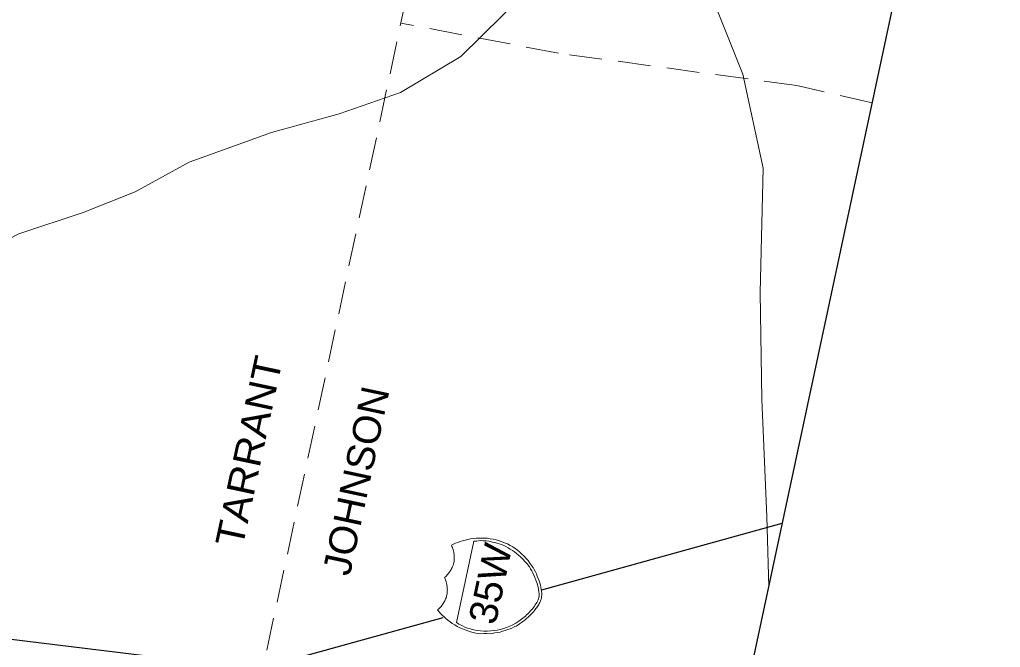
# Model space of a CAD drawing. Extents: x 2363411 to 2369126, y 6976878 to 6988319.
# Drawn here: x 2368374.1 to 2368553.7, y 6987987.6 to 6988102.7 of the extents above; entities that cross this region are included whole.
import ezdxf

# ---------------------------------------------------------------- set-up
doc = ezdxf.new("R2010")
doc.units = 0
doc.header["$LTSCALE"] = 2
doc.linetypes.add('MEDIUM_DASHED', pattern=[4.5, 3, -1.5])
doc.layers.add('62', color=7, linetype='Continuous', lineweight=13)
doc.layers.add('63', color=7, linetype='Continuous', lineweight=13)

msp = doc.modelspace()

# ---------------------------------------------------------------- linework, layer by layer
at = {"layer": '62', "linetype": 'MEDIUM_DASHED'}
msp.add_line((2368374.263, 6987775.914), (2368468.206, 6988215.584), dxfattribs=at)
at = {"layer": '62', "lineweight": 25}
msp.add_line((2368469.733, 6987998.18), (2368513.787, 6988010.419), dxfattribs=at)
for points in [[(2368004.774, 6987854.862), (2368459.776, 6987757.642), (2368553.719, 6988197.31), (2368098.715, 6988294.53)], [(2368243.911, 6988012.604), (2368291.866, 6988003.347), (2368346.556, 6987992.355), (2368417.518, 6987983.635), (2368451.697, 6987993.151)]]:
    msp.add_lwpolyline(points, dxfattribs=at)
at = {"layer": '62'}
for points in [[(2368423.495, 6988182.612), (2368431.049, 6988175.317), (2368445.358, 6988162.592), (2368462.419, 6988152.736), (2368475.776, 6988146.66), (2368485.116, 6988127.592), (2368494.927, 6988125.354), (2368500.711, 6988107.416), (2368506.585, 6988092.7), (2368510.293, 6988075.479), (2368509.748, 6988052.675), (2368510.031, 6988033.104), (2368510.965, 6988011.643), (2368511.296, 6987998.756)], [(2368492.126, 6988150.482), (2368487.488, 6988143.215), (2368483.673, 6988134.181), (2368476.579, 6988118.002), (2368468.319, 6988109.277), (2368462.564, 6988103.439), (2368454.914, 6988095.96), (2368443.897, 6988089.32), (2368432.645, 6988085.443), (2368420.226, 6988082.021), (2368405.209, 6988076.579), (2368395.275, 6988071.108), (2368385.769, 6988067.316), (2368374.006, 6988063.41), (2368368.396, 6988060.537), (2368354.465, 6988056.288)], [(2368452.564, 6988001.087), (2368452.692, 6988001.246), (2368452.823, 6988001.425), (2368452.92, 6988001.565), (2368453.05, 6988001.744), (2368453.137, 6988001.932), (2368453.24, 6988002.094), (2368453.321, 6988002.261), (2368453.386, 6988002.454), (2368453.467, 6988002.62), (2368453.554, 6988002.81), (2368453.592, 6988002.986), (2368453.634, 6988003.186), (2368453.673, 6988003.36), (2368453.709, 6988003.534), (2368453.711, 6988003.765), (2368453.702, 6988003.928), (2368453.716, 6988004.109), (2368453.716, 6988004.316), (2368453.691, 6988004.53), (2368453.685, 6988004.715), (2368453.64, 6988004.931), (2368453.612, 6988005.121), (2368453.562, 6988005.316), (2368453.512, 6988005.511), (2368453.461, 6988005.706), (2368453.392, 6988005.927), (2368453.301, 6988006.153), (2368453.208, 6988006.359), (2368453.571, 6988006.556), (2368453.954, 6988006.729), (2368454.357, 6988006.895), (2368454.805, 6988007.051), (2368455.227, 6988007.194), (2368455.691, 6988007.323), (2368456.175, 6988007.429), (2368456.68, 6988007.527), (2368457.2, 6988007.6), (2368457.718, 6988007.651), (2368458.252, 6988007.672), (2368458.759, 6988007.68), (2368459.284, 6988007.66), (2368459.809, 6988007.64), (2368460.321, 6988007.555), (2368460.837, 6988007.492), (2368461.377, 6988007.33), (2368461.924, 6988007.188), (2368462.455, 6988006.985), (2368462.947, 6988006.808), (2368463.457, 6988006.609), (2368463.947, 6988006.32), (2368464.422, 6988006.057), (2368464.866, 6988005.778), (2368465.305, 6988005.453), (2368465.736, 6988005.11), (2368466.121, 6988004.751), (2368466.526, 6988004.387), (2368466.896, 6988003.964), (2368467.241, 6988003.543), (2368467.587, 6988003.103), (2368467.896, 6988002.621), (2368468.143, 6988002.27), (2368468.363, 6988001.902), (2368468.574, 6988001.487), (2368468.768, 6988001.1), (2368468.929, 6988000.675), (2368469.092, 6988000.247), (2368469.237, 6987999.848), (2368469.382, 6987999.451), (2368469.504, 6987999.057), (2368469.585, 6987998.671), (2368469.663, 6987998.287), (2368469.721, 6987997.908), (2368469.742, 6987997.578), (2368469.741, 6987997.257), (2368469.719, 6987996.939), (2368469.686, 6987996.67)], [(2368469.686, 6987996.67), (2368469.625, 6987996.499), (2368469.593, 6987996.346), (2368469.534, 6987996.175), (2368469.457, 6987996.032), (2368469.374, 6987995.863), (2368469.294, 6987995.696), (2368469.179, 6987995.49), (2368469.072, 6987995.304), (2368468.947, 6987995.149), (2368468.837, 6987994.966), (2368468.681, 6987994.766), (2368468.551, 6987994.587), (2368468.414, 6987994.387), (2368468.269, 6987994.236), (2368468.088, 6987994.042), (2368467.931, 6987993.847), (2368467.757, 6987993.677), (2368467.577, 6987993.484), (2368467.383, 6987993.321), (2368467.209, 6987993.15), (2368467.032, 6987992.979), (2368466.815, 6987992.821), (2368466.64, 6987992.65), (2368466.448, 6987992.507), (2368466.23, 6987992.347), (2368466.038, 6987992.204), (2368465.848, 6987992.06), (2368465.638, 6987991.944), (2368465.42, 6987991.784), (2368465.235, 6987991.662), (2368465.028, 6987991.567), (2368464.819, 6987991.452), (2368464.411, 6987991.263), (2368463.93, 6987991.065), (2368463.485, 6987990.909), (2368463.036, 6987990.753), (2368462.568, 6987990.599), (2368462.103, 6987990.468), (2368461.643, 6987990.359), (2368461.168, 6987990.299), (2368460.69, 6987990.217), (2368460.196, 6987990.161), (2368459.692, 6987990.177), (2368459.207, 6987990.166), (2368458.699, 6987990.158), (2368458.226, 6987990.214), (2368457.689, 6987990.284), (2368457.178, 6987990.366), (2368456.68, 6987990.522), (2368456.183, 6987990.673), (2368455.692, 6987990.848), (2368455.204, 6987991.042), (2368454.743, 6987991.257), (2368454.266, 6987991.498), (2368453.816, 6987991.754), (2368453.364, 6987992.012), (2368452.948, 6987992.332), (2368452.55, 6987992.621), (2368452.181, 6987992.931), (2368451.852, 6987993.231), (2368451.511, 6987993.582), (2368451.205, 6987993.854), (2368450.931, 6987994.188), (2368450.678, 6987994.518), (2368450.847, 6987994.666), (2368451.022, 6987994.835), (2368451.176, 6987995.011), (2368451.302, 6987995.168), (2368451.432, 6987995.347), (2368451.556, 6987995.505), (2368451.665, 6987995.688), (2368451.79, 6987995.847), (2368451.871, 6987996.012), (2368451.975, 6987996.174), (2368452.061, 6987996.362), (2368452.122, 6987996.533), (2368452.212, 6987996.747), (2368452.29, 6987996.89), (2368452.328, 6987997.066), (2368452.374, 6987997.285), (2368452.411, 6987997.461), (2368452.449, 6987997.637), (2368452.448, 6987997.844), (2368452.442, 6987998.029), (2368452.456, 6987998.21), (2368452.449, 6987998.396), (2368452.43, 6987998.631), (2368452.426, 6987998.818), (2368452.375, 6987999.013), (2368452.346, 6987999.203), (2368452.3, 6987999.42), (2368452.254, 6987999.636), (2368452.204, 6987999.831), (2368452.133, 6988000.03), (2368452.039, 6988000.236), (2368451.949, 6988000.46), (2368452.116, 6988000.608), (2368452.287, 6988000.756), (2368452.439, 6988000.932), (2368452.564, 6988001.087)]]:
    msp.add_lwpolyline(points, dxfattribs=at)
at = {"layer": '62', "linetype": 'MEDIUM_DASHED'}
msp.add_lwpolyline([(2368530.249, 6988087.461), (2368516.424, 6988090.6), (2368472.799, 6988096.536), (2368443.949, 6988102.056)], dxfattribs=at)
at = {"layer": '62'}
msp.add_lwpolyline([(2368457.299, 6988007.096), (2368454.117, 6987992.197), (2368454.318, 6987992.064), (2368454.584, 6987991.913), (2368454.872, 6987991.759), (2368455.252, 6987991.586), (2368455.669, 6987991.382), (2368456.155, 6987991.186), (2368456.673, 6987991.029), (2368457.292, 6987990.894), (2368457.885, 6987990.772), (2368458.535, 6987990.678), (2368459.146, 6987990.639), (2368459.769, 6987990.643), (2368460.397, 6987990.671), (2368460.984, 6987990.729), (2368461.598, 6987990.805), (2368462.183, 6987990.956), (2368462.745, 6987991.112), (2368463.313, 6987991.291), (2368463.894, 6987991.535), (2368464.452, 6987991.782), (2368464.981, 6987992.106), (2368465.518, 6987992.452), (2368466.008, 6987992.807), (2368466.506, 6987993.208), (2368466.752, 6987993.385), (2368466.963, 6987993.616), (2368467.212, 6987993.816), (2368467.428, 6987994.068), (2368467.635, 6987994.28), (2368467.865, 6987994.505), (2368468.031, 6987994.745), (2368468.242, 6987994.977), (2368468.409, 6987995.217), (2368468.547, 6987995.441), (2368468.716, 6987995.683), (2368468.85, 6987995.883), (2368468.973, 6987996.131), (2368469.063, 6987996.343), (2368469.132, 6987996.559), (2368469.201, 6987996.776), (2368469.245, 6987997.089), (2368469.26, 6987997.475), (2368469.203, 6987997.855), (2368469.154, 6987998.281), (2368469.081, 6987998.685), (2368468.966, 6987999.125), (2368468.827, 6987999.547), (2368468.671, 6987999.993), (2368468.49, 6988000.447), (2368468.284, 6988000.882), (2368468.097, 6988001.29), (2368467.903, 6988001.677), (2368467.71, 6988002.064), (2368467.484, 6988002.411), (2368467.253, 6988002.736), (2368467.049, 6988002.964), (2368466.662, 6988003.415), (2368466.283, 6988003.794), (2368465.906, 6988004.174), (2368465.501, 6988004.536), (2368465.132, 6988004.869), (2368464.735, 6988005.164), (2368464.355, 6988005.427), (2368463.948, 6988005.676), (2368463.562, 6988005.918), (2368463.174, 6988006.14), (2368462.773, 6988006.32), (2368462.349, 6988006.478), (2368461.943, 6988006.632), (2368461.535, 6988006.766), (2368461.119, 6988006.877), (2368460.725, 6988006.962), (2368460.106, 6988007.094), (2368459.571, 6988007.163), (2368459.043, 6988007.184), (2368458.591, 6988007.211), (2368458.17, 6988007.186), (2368457.838, 6988007.141), (2368457.533, 6988007.114)], close=True, dxfattribs=at)
at = {"layer": '63', "linetype": 'MEDIUM_DASHED'}
msp.add_line((2368374.263, 6987775.914), (2368468.206, 6988215.584), dxfattribs=at)
at = {"layer": '63', "lineweight": 25}
msp.add_line((2368469.733, 6987998.18), (2368513.787, 6988010.419), dxfattribs=at)
for points in [[(2368004.774, 6987854.862), (2368459.776, 6987757.642), (2368553.719, 6988197.31), (2368098.715, 6988294.53)], [(2368243.911, 6988012.604), (2368291.866, 6988003.347), (2368346.556, 6987992.355), (2368417.518, 6987983.635), (2368451.697, 6987993.151)]]:
    msp.add_lwpolyline(points, dxfattribs=at)
at = {"layer": '63'}
for points in [[(2368423.495, 6988182.612), (2368431.049, 6988175.317), (2368445.358, 6988162.592), (2368462.419, 6988152.736), (2368475.776, 6988146.66), (2368485.116, 6988127.592), (2368494.927, 6988125.354), (2368500.711, 6988107.416), (2368506.585, 6988092.7), (2368510.293, 6988075.479), (2368509.748, 6988052.675), (2368510.031, 6988033.104), (2368510.965, 6988011.643), (2368511.296, 6987998.756)], [(2368492.126, 6988150.482), (2368487.488, 6988143.215), (2368483.673, 6988134.181), (2368476.579, 6988118.002), (2368468.319, 6988109.277), (2368462.564, 6988103.439), (2368454.914, 6988095.96), (2368443.897, 6988089.32), (2368432.645, 6988085.443), (2368420.226, 6988082.021), (2368405.209, 6988076.579), (2368395.275, 6988071.108), (2368385.769, 6988067.316), (2368374.006, 6988063.41), (2368368.396, 6988060.537), (2368354.465, 6988056.288)], [(2368452.564, 6988001.087), (2368452.692, 6988001.246), (2368452.823, 6988001.425), (2368452.92, 6988001.565), (2368453.05, 6988001.744), (2368453.137, 6988001.932), (2368453.24, 6988002.094), (2368453.321, 6988002.261), (2368453.386, 6988002.454), (2368453.467, 6988002.62), (2368453.554, 6988002.81), (2368453.592, 6988002.986), (2368453.634, 6988003.186), (2368453.673, 6988003.36), (2368453.709, 6988003.534), (2368453.711, 6988003.765), (2368453.702, 6988003.928), (2368453.716, 6988004.109), (2368453.716, 6988004.316), (2368453.691, 6988004.53), (2368453.685, 6988004.715), (2368453.64, 6988004.931), (2368453.612, 6988005.121), (2368453.562, 6988005.316), (2368453.512, 6988005.511), (2368453.461, 6988005.706), (2368453.392, 6988005.927), (2368453.301, 6988006.153), (2368453.208, 6988006.359), (2368453.571, 6988006.556), (2368453.954, 6988006.729), (2368454.357, 6988006.895), (2368454.805, 6988007.051), (2368455.227, 6988007.194), (2368455.691, 6988007.323), (2368456.175, 6988007.429), (2368456.68, 6988007.527), (2368457.2, 6988007.6), (2368457.718, 6988007.651), (2368458.252, 6988007.672), (2368458.759, 6988007.68), (2368459.284, 6988007.66), (2368459.809, 6988007.64), (2368460.321, 6988007.555), (2368460.837, 6988007.492), (2368461.377, 6988007.33), (2368461.924, 6988007.188), (2368462.455, 6988006.985), (2368462.947, 6988006.808), (2368463.457, 6988006.609), (2368463.947, 6988006.32), (2368464.422, 6988006.057), (2368464.866, 6988005.778), (2368465.305, 6988005.453), (2368465.736, 6988005.11), (2368466.121, 6988004.751), (2368466.526, 6988004.387), (2368466.896, 6988003.964), (2368467.241, 6988003.543), (2368467.587, 6988003.103), (2368467.896, 6988002.621), (2368468.143, 6988002.27), (2368468.363, 6988001.902), (2368468.574, 6988001.487), (2368468.768, 6988001.1), (2368468.929, 6988000.675), (2368469.092, 6988000.247), (2368469.237, 6987999.848), (2368469.382, 6987999.451), (2368469.504, 6987999.057), (2368469.585, 6987998.671), (2368469.663, 6987998.287), (2368469.721, 6987997.908), (2368469.742, 6987997.578), (2368469.741, 6987997.257), (2368469.719, 6987996.939), (2368469.686, 6987996.67)], [(2368469.686, 6987996.67), (2368469.625, 6987996.499), (2368469.593, 6987996.346), (2368469.534, 6987996.175), (2368469.457, 6987996.032), (2368469.374, 6987995.863), (2368469.294, 6987995.696), (2368469.179, 6987995.49), (2368469.072, 6987995.304), (2368468.947, 6987995.149), (2368468.837, 6987994.966), (2368468.681, 6987994.766), (2368468.551, 6987994.587), (2368468.414, 6987994.387), (2368468.269, 6987994.236), (2368468.088, 6987994.042), (2368467.931, 6987993.847), (2368467.757, 6987993.677), (2368467.577, 6987993.484), (2368467.383, 6987993.321), (2368467.209, 6987993.15), (2368467.032, 6987992.979), (2368466.815, 6987992.821), (2368466.64, 6987992.65), (2368466.448, 6987992.507), (2368466.23, 6987992.347), (2368466.038, 6987992.204), (2368465.848, 6987992.06), (2368465.638, 6987991.944), (2368465.42, 6987991.784), (2368465.235, 6987991.662), (2368465.028, 6987991.567), (2368464.819, 6987991.452), (2368464.411, 6987991.263), (2368463.93, 6987991.065), (2368463.485, 6987990.909), (2368463.036, 6987990.753), (2368462.568, 6987990.599), (2368462.103, 6987990.468), (2368461.643, 6987990.359), (2368461.168, 6987990.299), (2368460.69, 6987990.217), (2368460.196, 6987990.161), (2368459.692, 6987990.177), (2368459.207, 6987990.166), (2368458.699, 6987990.158), (2368458.226, 6987990.214), (2368457.689, 6987990.284), (2368457.178, 6987990.366), (2368456.68, 6987990.522), (2368456.183, 6987990.673), (2368455.692, 6987990.848), (2368455.204, 6987991.042), (2368454.743, 6987991.257), (2368454.266, 6987991.498), (2368453.816, 6987991.754), (2368453.364, 6987992.012), (2368452.948, 6987992.332), (2368452.55, 6987992.621), (2368452.181, 6987992.931), (2368451.852, 6987993.231), (2368451.511, 6987993.582), (2368451.205, 6987993.854), (2368450.931, 6987994.188), (2368450.678, 6987994.518), (2368450.847, 6987994.666), (2368451.022, 6987994.835), (2368451.176, 6987995.011), (2368451.302, 6987995.168), (2368451.432, 6987995.347), (2368451.556, 6987995.505), (2368451.665, 6987995.688), (2368451.79, 6987995.847), (2368451.871, 6987996.012), (2368451.975, 6987996.174), (2368452.061, 6987996.362), (2368452.122, 6987996.533), (2368452.212, 6987996.747), (2368452.29, 6987996.89), (2368452.328, 6987997.066), (2368452.374, 6987997.285), (2368452.411, 6987997.461), (2368452.449, 6987997.637), (2368452.448, 6987997.844), (2368452.442, 6987998.029), (2368452.456, 6987998.21), (2368452.449, 6987998.396), (2368452.43, 6987998.631), (2368452.426, 6987998.818), (2368452.375, 6987999.013), (2368452.346, 6987999.203), (2368452.3, 6987999.42), (2368452.254, 6987999.636), (2368452.204, 6987999.831), (2368452.133, 6988000.03), (2368452.039, 6988000.236), (2368451.949, 6988000.46), (2368452.116, 6988000.608), (2368452.287, 6988000.756), (2368452.439, 6988000.932), (2368452.564, 6988001.087)]]:
    msp.add_lwpolyline(points, dxfattribs=at)
at = {"layer": '63', "linetype": 'MEDIUM_DASHED'}
msp.add_lwpolyline([(2368530.249, 6988087.461), (2368516.424, 6988090.6), (2368472.799, 6988096.536), (2368443.949, 6988102.056)], dxfattribs=at)
at = {"layer": '63'}
msp.add_lwpolyline([(2368457.299, 6988007.096), (2368454.117, 6987992.197), (2368454.318, 6987992.064), (2368454.584, 6987991.913), (2368454.872, 6987991.759), (2368455.252, 6987991.586), (2368455.669, 6987991.382), (2368456.155, 6987991.186), (2368456.673, 6987991.029), (2368457.292, 6987990.894), (2368457.885, 6987990.772), (2368458.535, 6987990.678), (2368459.146, 6987990.639), (2368459.769, 6987990.643), (2368460.397, 6987990.671), (2368460.984, 6987990.729), (2368461.598, 6987990.805), (2368462.183, 6987990.956), (2368462.745, 6987991.112), (2368463.313, 6987991.291), (2368463.894, 6987991.535), (2368464.452, 6987991.782), (2368464.981, 6987992.106), (2368465.518, 6987992.452), (2368466.008, 6987992.807), (2368466.506, 6987993.208), (2368466.752, 6987993.385), (2368466.963, 6987993.616), (2368467.212, 6987993.816), (2368467.428, 6987994.068), (2368467.635, 6987994.28), (2368467.865, 6987994.505), (2368468.031, 6987994.745), (2368468.242, 6987994.977), (2368468.409, 6987995.217), (2368468.547, 6987995.441), (2368468.716, 6987995.683), (2368468.85, 6987995.883), (2368468.973, 6987996.131), (2368469.063, 6987996.343), (2368469.132, 6987996.559), (2368469.201, 6987996.776), (2368469.245, 6987997.089), (2368469.26, 6987997.475), (2368469.203, 6987997.855), (2368469.154, 6987998.281), (2368469.081, 6987998.685), (2368468.966, 6987999.125), (2368468.827, 6987999.547), (2368468.671, 6987999.993), (2368468.49, 6988000.447), (2368468.284, 6988000.882), (2368468.097, 6988001.29), (2368467.903, 6988001.677), (2368467.71, 6988002.064), (2368467.484, 6988002.411), (2368467.253, 6988002.736), (2368467.049, 6988002.964), (2368466.662, 6988003.415), (2368466.283, 6988003.794), (2368465.906, 6988004.174), (2368465.501, 6988004.536), (2368465.132, 6988004.869), (2368464.735, 6988005.164), (2368464.355, 6988005.427), (2368463.948, 6988005.676), (2368463.562, 6988005.918), (2368463.174, 6988006.14), (2368462.773, 6988006.32), (2368462.349, 6988006.478), (2368461.943, 6988006.632), (2368461.535, 6988006.766), (2368461.119, 6988006.877), (2368460.725, 6988006.962), (2368460.106, 6988007.094), (2368459.571, 6988007.163), (2368459.043, 6988007.184), (2368458.591, 6988007.211), (2368458.17, 6988007.186), (2368457.838, 6988007.141), (2368457.533, 6988007.114)], close=True, dxfattribs=at)

# ---------------------------------------------------------------- texts
at = {"layer": '62'}
for s, width, p in [('TARRANT', 1.1, (2368414.922, 6988005.724)), ('JOHNSON', 1.05, (2368434.575, 6988000.559)), ('35W', 1.05, (2368461.262, 6987991.591))]:
    msp.add_text(s, height=5.099, rotation=77.939, dxfattribs=dict(at, width=width)).set_placement(p)
at = {"layer": '63'}
for s, width, p in [('TARRANT', 1.1, (2368414.922, 6988005.724)), ('JOHNSON', 1.05, (2368434.575, 6988000.559)), ('35W', 1.05, (2368461.262, 6987991.591))]:
    msp.add_text(s, height=5.099, rotation=77.939, dxfattribs=dict(at, width=width)).set_placement(p)

doc.saveas('drawing.dxf')
